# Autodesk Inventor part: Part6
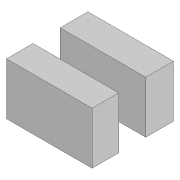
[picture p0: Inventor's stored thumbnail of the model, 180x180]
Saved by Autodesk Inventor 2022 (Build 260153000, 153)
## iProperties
Created: 2015-07
Part Number: Part6
Material: Generic
Document SubType Name: Modeling
Designer: Sandeep
Density: 1 g/cm^3
Appearance: Default
Author: Sandeep
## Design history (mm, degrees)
sketch "Sketch1"
  geometry: L1 (-17.042, 14.133)-(12.609, 14.133); L2 (12.609, 14.133)-(12.609, -14.063); L3 (12.609, -14.063)-(-17.042, -14.063); L4 (-17.042, -14.063)-(-17.042, 14.133); 1 further point
  constraints: 8 end point, 2 parallel, 1 horizontal, 1 perpendicular
extrude "Extrusion1" new body sketch "Sketch1" distance "d0" = 18; taper "d1" = 0 deg
sketch "Sketch2"
  geometry: L1 (-18, 28.196)-(-18, 0) reference; L2 (-18, 9.203)-(0.196, 9.203); L3 (0.196, 9.203)-(0.196, 18.574); L4 (0.196, 18.574)-(-18, 18.574); L5 (-18, 18.574)-(-18, 9.203); 1 further point
  constraints: 8 end point, 2 parallel, 1 horizontal, 1 perpendicular, 1 point on line
extrude "Extrusion2" cut sketch "Sketch2" distance "d2" = 8; taper "d3" = 0 deg
node "Direct Edit1"
body "Solid1"
feature "Delete1"
